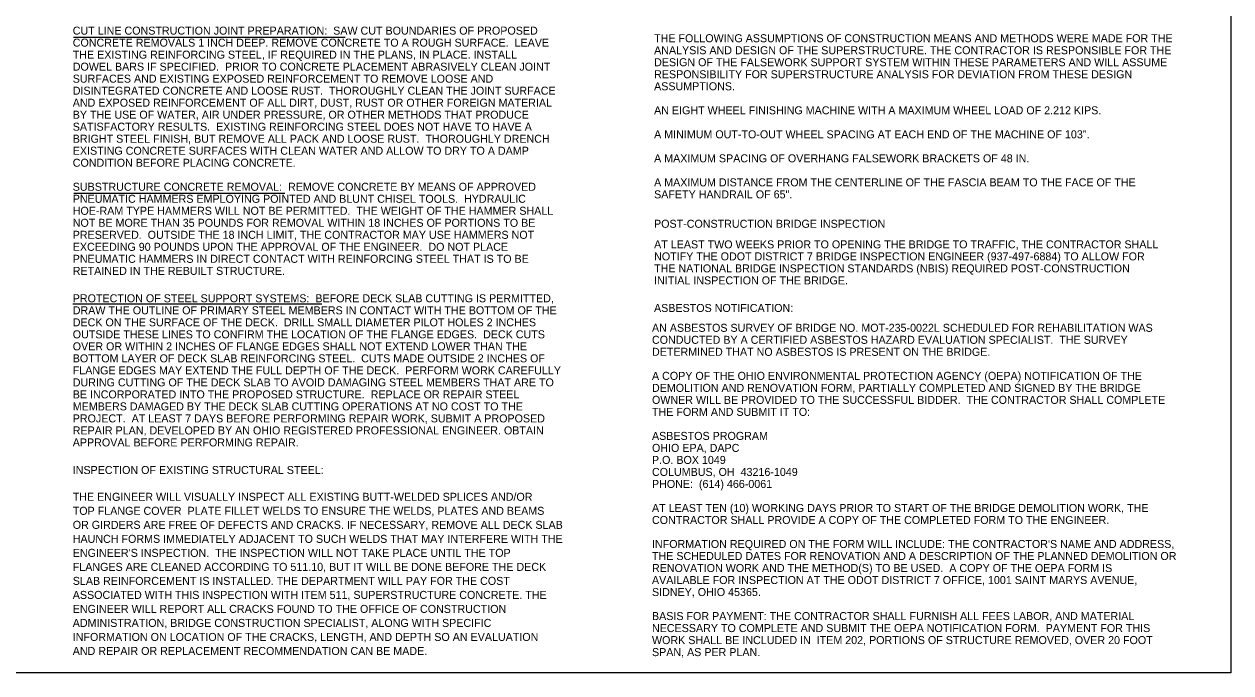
# Model space of a CAD drawing. Extents: x -10.6 to 33.4, y -28.4 to 21.5.
# Drawn here: x 11.39 to 32.5, y -28.43 to -17.08 of the extents above; entities that cross this region are included whole.
import ezdxf

# ---------------------------------------------------------------- set-up
doc = ezdxf.new("R2010")
doc.units = 0
for name, color, linetype in [('BR_P_Gen_Text', 7, 'Continuous'), ('Default', 7, 'Continuous'), ('SC_Scratch1', 7, 'Continuous')]:
    doc.layers.add(name, color=color, linetype=linetype)

msp = doc.modelspace()

# ---------------------------------------------------------------- linework, layer by layer
at = {"layer": 'BR_P_Gen_Text'}
for p, q in [((12.257, -17.311), (17.008, -17.311)), ((12.263, -20.04), (15.95, -20.04)), ((12.243, -21.977), (16.598, -21.977))]:
    msp.add_line(p, q, dxfattribs=at)
at = {"layer": 'SC_Scratch1'}
msp.add_lwpolyline([(2, -7.427), (32.5, -7.427), (32.5, -28.427), (2, -28.427)], close=True, dxfattribs=at)

# ---------------------------------------------------------------- texts
at = {"layer": 'BR_P_Gen_Text'}
for s, p in [('THE FOLLOWING ASSUMPTIONS OF CONSTRUCTION MEANS AND METHODS WERE MADE FOR THE ', (22.411, -17.401)), ('ANALYSIS AND DESIGN OF THE SUPERSTRUCTURE. THE CONTRACTOR IS RESPONSIBLE FOR THE ', (22.411, -17.611)), ('DESIGN OF THE FALSEWORK SUPPORT SYSTEM WITHIN THESE PARAMETERS AND WILL ASSUME ', (22.411, -17.821)), ('RESPONSIBILITY FOR SUPERSTRUCTURE ANALYSIS FOR DEVIATION FROM THESE DESIGN ', (22.411, -18.031)), ('ASSUMPTIONS. ', (22.411, -18.241)), ('AN EIGHT WHEEL FINISHING MACHINE WITH A MAXIMUM WHEEL LOAD OF 2.212 KIPS.', (22.411, -18.661)), ('A MINIMUM OUT-TO-OUT WHEEL SPACING AT EACH END OF THE MACHINE OF 103". ', (22.411, -19.081)), ('A MAXIMUM SPACING OF OVERHANG FALSEWORK BRACKETS OF 48 IN. ', (22.411, -19.501)), ('A MAXIMUM DISTANCE FROM THE CENTERLINE OF THE FASCIA BEAM TO THE FACE OF THE ', (22.411, -19.921)), ('SAFETY HANDRAIL OF 65".', (22.411, -20.131)), ('AT LEAST TWO WEEKS PRIOR TO OPENING THE BRIDGE TO TRAFFIC, THE CONTRACTOR SHALL ', (22.411, -21.005)), ('NOTIFY THE ODOT DISTRICT 7 BRIDGE INSPECTION ENGINEER (937-497-6884) TO ALLOW FOR ', (22.411, -21.215)), ('THE NATIONAL BRIDGE INSPECTION STANDARDS (NBIS) REQUIRED POST-CONSTRUCTION ', (22.411, -21.425)), ('INITIAL INSPECTION OF THE BRIDGE.', (22.411, -21.635)), ('INSPECTION OF EXISTING STRUCTURAL STEEL:', (12.242, -24.95)), ('THE ENGINEER WILL VISUALLY INSPECT ALL EXISTING BUTT-WELDED SPLICES AND/OR', (12.242, -25.419)), ('TOP FLANGE COVER  PLATE FILLET WELDS TO ENSURE THE WELDS, PLATES AND BEAMS', (12.242, -25.664)), ('OR GIRDERS ARE FREE OF DEFECTS AND CRACKS. IF NECESSARY, REMOVE ALL DECK SLAB', (12.242, -25.909)), ('HAUNCH FORMS IMMEDIATELY ADJACENT TO SUCH WELDS THAT MAY INTERFERE WITH THE', (12.242, -26.154)), ("ENGINEER'S INSPECTION.  THE INSPECTION WILL NOT TAKE PLACE UNTIL THE TOP ", (12.242, -26.399)), ('FLANGES ARE CLEANED ACCORDING TO 511.10, BUT IT WILL BE DONE BEFORE THE DECK', (12.242, -26.644)), ('SLAB REINFORCEMENT IS INSTALLED. THE DEPARTMENT WILL PAY FOR THE COST ', (12.242, -26.889)), ('ASSOCIATED WITH THIS INSPECTION WITH ITEM 511, SUPERSTRUCTURE CONCRETE. THE', (12.242, -27.134)), ('ENGINEER WILL REPORT ALL CRACKS FOUND TO THE OFFICE OF CONSTRUCTION ', (12.242, -27.379)), ('ADMINISTRATION, BRIDGE CONSTRUCTION SPECIALIST, ALONG WITH SPECIFIC', (12.242, -27.624)), ('INFORMATION ON LOCATION OF THE CRACKS, LENGTH, AND DEPTH SO AN EVALUATION', (12.242, -27.869)), ('AND REPAIR OR REPLACEMENT RECOMMENDATION CAN BE MADE.', (12.242, -28.114))]:
    msp.add_text(s, height=0.14, dxfattribs=at).set_placement(p)
at = {"layer": 'Default'}
for s, p in [('CUT LINE CONSTRUCTION JOINT PREPARATION:  SAW CUT BOUNDARIES OF PROPOSED ', (12.242, -17.268)), ('CONCRETE REMOVALS 1 INCH DEEP. REMOVE CONCRETE TO A ROUGH SURFACE.  LEAVE ', (12.242, -17.478)), ('THE EXISTING REINFORCING STEEL, IF REQUIRED IN THE PLANS, IN PLACE. INSTALL ', (12.242, -17.688)), ('DOWEL BARS IF SPECIFIED.  PRIOR TO CONCRETE PLACEMENT ABRASIVELY CLEAN JOINT ', (12.242, -17.898)), ('SURFACES AND EXISTING EXPOSED REINFORCEMENT TO REMOVE LOOSE AND ', (12.242, -18.108)), ('DISINTEGRATED CONCRETE AND LOOSE RUST.  THOROUGHLY CLEAN THE JOINT SURFACE ', (12.242, -18.318)), ('AND EXPOSED REINFORCEMENT OF ALL DIRT, DUST, RUST OR OTHER FOREIGN MATERIAL ', (12.242, -18.528)), ('BY THE USE OF WATER, AIR UNDER PRESSURE, OR OTHER METHODS THAT PRODUCE ', (12.242, -18.738)), ('SATISFACTORY RESULTS.  EXISTING REINFORCING STEEL DOES NOT HAVE TO HAVE A ', (12.242, -18.948)), ('BRIGHT STEEL FINISH, BUT REMOVE ALL PACK AND LOOSE RUST.  THOROUGHLY DRENCH ', (12.242, -19.158)), ('EXISTING CONCRETE SURFACES WITH CLEAN WATER AND ALLOW TO DRY TO A DAMP ', (12.242, -19.368)), ('CONDITION BEFORE PLACING CONCRETE.', (12.242, -19.578)), ('SUBSTRUCTURE CONCRETE REMOVAL:  REMOVE CONCRETE BY MEANS OF APPROVED ', (12.242, -19.998)), ('PNEUMATIC HAMMERS EMPLOYING POINTED AND BLUNT CHISEL TOOLS.  HYDRAULIC ', (12.242, -20.208)), ('HOE-RAM TYPE HAMMERS WILL NOT BE PERMITTED.  THE WEIGHT OF THE HAMMER SHALL ', (12.242, -20.418)), ('NOT BE MORE THAN 35 POUNDS FOR REMOVAL WITHIN 18 INCHES OF PORTIONS TO BE ', (12.242, -20.628)), ('POST-CONSTRUCTION BRIDGE INSPECTION', (22.41, -20.645)), ('PRESERVED.  OUTSIDE THE 18 INCH LIMIT, THE CONTRACTOR MAY USE HAMMERS NOT ', (12.242, -20.838)), ('EXCEEDING 90 POUNDS UPON THE APPROVAL OF THE ENGINEER.  DO NOT PLACE ', (12.242, -21.048)), ('PNEUMATIC HAMMERS IN DIRECT CONTACT WITH REINFORCING STEEL THAT IS TO BE ', (12.242, -21.258)), ('RETAINED IN THE REBUILT STRUCTURE. ', (12.242, -21.468)), ('PROTECTION OF STEEL SUPPORT SYSTEMS:  BEFORE DECK SLAB CUTTING IS PERMITTED, ', (12.242, -21.948)), ('DRAW THE OUTLINE OF PRIMARY STEEL MEMBERS IN CONTACT WITH THE BOTTOM OF THE ', (12.242, -22.158)), ('ASBESTOS NOTIFICATION:', (22.41, -22.117)), ('DECK ON THE SURFACE OF THE DECK.  DRILL SMALL DIAMETER PILOT HOLES 2 INCHES ', (12.242, -22.368)), ('AN ASBESTOS SURVEY OF BRIDGE NO. MOT-235-0022L SCHEDULED FOR REHABILITATION WAS ', (22.374, -22.464)), ('OUTSIDE THESE LINES TO CONFIRM THE LOCATION OF THE FLANGE EDGES.  DECK CUTS ', (12.242, -22.578)), ('CONDUCTED BY A CERTIFIED ASBESTOS HAZARD EVALUATION SPECIALIST.  THE SURVEY ', (22.374, -22.674)), ('OVER OR WITHIN 2 INCHES OF FLANGE EDGES SHALL NOT EXTEND LOWER THAN THE ', (12.242, -22.788)), ('DETERMINED THAT NO ASBESTOS IS PRESENT ON THE BRIDGE.', (22.374, -22.884)), ('BOTTOM LAYER OF DECK SLAB REINFORCING STEEL.  CUTS MADE OUTSIDE 2 INCHES OF ', (12.242, -22.998)), ('FLANGE EDGES MAY EXTEND THE FULL DEPTH OF THE DECK.  PERFORM WORK CAREFULLY ', (12.242, -23.208)), ('A COPY OF THE OHIO ENVIRONMENTAL PROTECTION AGENCY (OEPA) NOTIFICATION OF THE ', (22.374, -23.304)), ('DURING CUTTING OF THE DECK SLAB TO AVOID DAMAGING STEEL MEMBERS THAT ARE TO ', (12.242, -23.418)), ('DEMOLITION AND RENOVATION FORM, PARTIALLY COMPLETED AND SIGNED BY THE BRIDGE ', (22.374, -23.514)), ('BE INCORPORATED INTO THE PROPOSED STRUCTURE.  REPLACE OR REPAIR STEEL ', (12.242, -23.628)), ('OWNER WILL BE PROVIDED TO THE SUCCESSFUL BIDDER.  THE CONTRACTOR SHALL COMPLETE ', (22.374, -23.724)), ('MEMBERS DAMAGED BY THE DECK SLAB CUTTING OPERATIONS AT NO COST TO THE ', (12.242, -23.838)), ('THE FORM AND SUBMIT IT TO:', (22.374, -23.934)), ('PROJECT.  AT LEAST 7 DAYS BEFORE PERFORMING REPAIR WORK, SUBMIT A PROPOSED ', (12.242, -24.048)), ('REPAIR PLAN, DEVELOPED BY AN OHIO REGISTERED PROFESSIONAL ENGINEER. OBTAIN ', (12.242, -24.258)), ('ASBESTOS PROGRAM', (22.374, -24.354)), ('APPROVAL BEFORE PERFORMING REPAIR.', (12.242, -24.468)), ('OHIO EPA, DAPC', (22.374, -24.564)), ('P.O. BOX 1049', (22.374, -24.774)), ('COLUMBUS, OH  43216-1049', (22.374, -24.984)), ('PHONE:  (614) 466-0061', (22.374, -25.194)), ('AT LEAST TEN (10) WORKING DAYS PRIOR TO START OF THE BRIDGE DEMOLITION WORK, THE ', (22.374, -25.614)), ('CONTRACTOR SHALL PROVIDE A COPY OF THE COMPLETED FORM TO THE ENGINEER.', (22.374, -25.824)), ("INFORMATION REQUIRED ON THE FORM WILL INCLUDE: THE CONTRACTOR'S NAME AND ADDRESS, ", (22.374, -26.244)), ('THE SCHEDULED DATES FOR RENOVATION AND A DESCRIPTION OF THE PLANNED DEMOLITION OR ', (22.374, -26.454)), ('RENOVATION WORK AND THE METHOD(S) TO BE USED.  A COPY OF THE OEPA FORM IS ', (22.374, -26.664)), ('AVAILABLE FOR INSPECTION AT THE ODOT DISTRICT 7 OFFICE, 1001 SAINT MARYS AVENUE, ', (22.374, -26.874)), ('SIDNEY, OHIO 45365.', (22.374, -27.084)), ('BASIS FOR PAYMENT: THE CONTRACTOR SHALL FURNISH ALL FEES LABOR, AND MATERIAL ', (22.374, -27.504)), ('NECESSARY TO COMPLETE AND SUBMIT THE OEPA NOTIFICATION FORM.  PAYMENT FOR THIS ', (22.374, -27.714)), ('WORK SHALL BE INCLUDED IN  ITEM 202, PORTIONS OF STRUCTURE REMOVED, OVER 20 FOOT ', (22.374, -27.924)), ('SPAN, AS PER PLAN.', (22.374, -28.134))]:
    msp.add_text(s, height=0.14, dxfattribs=at).set_placement(p)

doc.saveas('drawing.dxf')
